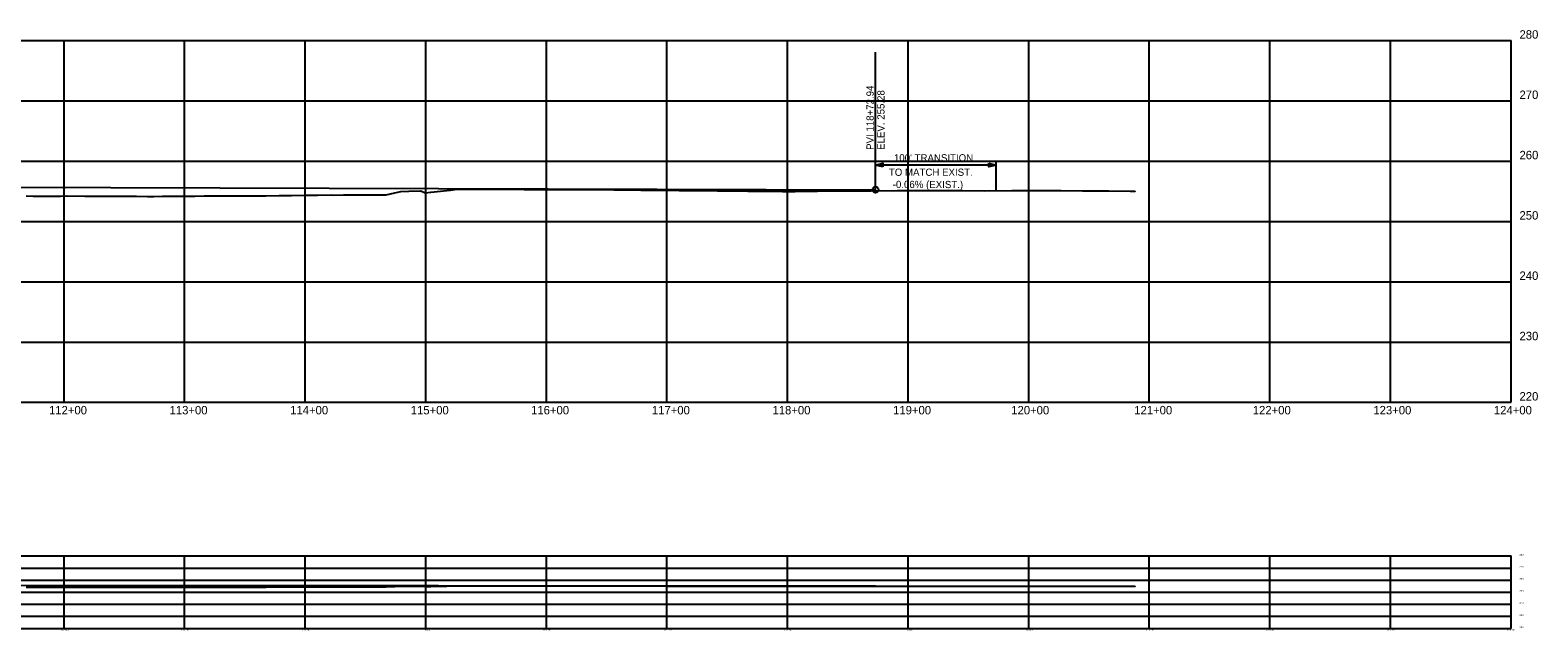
# Model space of a CAD drawing. Extents: x 1932071 to 1934815, y 598385 to 598883.
# Drawn here: x 1933565 to 1934815, y 598385 to 598883 of the extents above; entities that cross this region are included whole.
import ezdxf

# ---------------------------------------------------------------- set-up
doc = ezdxf.new("R2010")
doc.units = 0
for name, color, linetype in [('R_Annotation', 7, 'Continuous'), ('R_Axis', 7, 'Continuous'), ('R_Axis Annot', 7, 'Continuous'), ('R_Exist Surface', 7, 'Continuous'), ('R_Grid', 7, 'Continuous'), ('R_Vert Alg', 7, 'Continuous'), ('R_Vert Alg Annot', 7, 'Continuous')]:
    doc.layers.add(name, color=color, linetype=linetype)

msp = doc.modelspace()

# ---------------------------------------------------------------- linework, layer by layer
at = {"layer": 'R_Annotation'}
for p, q in [((1934265.6, 598750.9), (1934265.6, 598774.3)), ((1934365.6, 598771.3), (1934265.6, 598771.3)), ((1934365.6, 598750.9), (1934365.6, 598774.3))]:
    msp.add_line(p, q, dxfattribs=at)
for points in [[(1934271.6, 598769.8), (1934265.6, 598771.3), (1934271.6, 598772.8)], [(1934359.6, 598772.8), (1934365.6, 598771.3), (1934359.6, 598769.8)]]:
    msp.add_lwpolyline(points, close=True, dxfattribs=at)
at = {"layer": 'R_Axis'}
for p, q in [((1934392.7, 598874.6), (1934392.7, 598874.3)), ((1934792.7, 598574.6), (1934792.7, 598874.6)), ((1933692.7, 598824.6), (1933692.7, 598824.3)), ((1933692.7, 598824.6), (1933692.7, 598824.3)), ((1934192.7, 598824.6), (1934192.7, 598824.2)), ((1932092.7, 598574.6), (1934792.7, 598574.6)), ((1934392.7, 598447.2), (1934392.7, 598447.1)), ((1934392.7, 598447.2), (1934392.7, 598447.1)), ((1934792.7, 598387.2), (1934792.7, 598447.2)), ((1933692.7, 598437.2), (1933692.7, 598437.1)), ((1933692.7, 598437.2), (1933692.7, 598437.1)), ((1933692.7, 598437.2), (1933692.7, 598437.1)), ((1933692.7, 598437.2), (1933692.7, 598437.1)), ((1933692.7, 598437.2), (1933692.7, 598437.1)), ((1933692.7, 598437.2), (1933692.7, 598437.1)), ((1934192.7, 598437.2), (1934192.7, 598437.1)), ((1934192.7, 598437.2), (1934192.7, 598437.1)), ((1934192.7, 598437.2), (1934192.7, 598437.1)), ((1932092.7, 598387.2), (1934792.7, 598387.2))]:
    msp.add_line(p, q, dxfattribs=at)
at = {"layer": 'R_Exist Surface'}
for points in [[(1933561.3, 598745.7), (1933567.2, 598745.6), (1933584.5, 598745.5), (1933584.6, 598745.5), (1933584.8, 598745.5), (1933588.6, 598745.6), (1933589.6, 598745.6), (1933595, 598745.7), (1933595.3, 598745.7), (1933610, 598745.6), (1933612.3, 598745.6), (1933613.5, 598745.6), (1933629.9, 598745.5), (1933631.5, 598745.5), (1933632.5, 598745.5), (1933648, 598745.4), (1933652.9, 598745.4), (1933662, 598745.3), (1933667.1, 598745.3), (1933674.3, 598745.4), (1933682.7, 598745.5), (1933690.1, 598745.4), (1933695.7, 598745.5), (1933701.2, 598745.6), (1933709, 598745.7), (1933717.2, 598745.8), (1933722.5, 598745.8), (1933729, 598745.8), (1933729.5, 598745.8), (1933738.6, 598745.8), (1933750, 598745.8), (1933751.7, 598745.8), (1933760, 598745.9), (1933771.1, 598746.1), (1933773.3, 598746.1), (1933781.4, 598746.2), (1933792.2, 598746.4), (1933794.9, 598746.4), (1933802.9, 598746.4), (1933814.2, 598746.5), (1933816.1, 598746.4), (1933824.3, 598746.5), (1933836.4, 598746.6), (1933837.4, 598746.5), (1933845.7, 598746.6), (1933857.8, 598746.6), (1933859.9, 598746.6), (1933867.1, 598748.3), (1933872, 598749.4), (1933878.5, 598749.6), (1933888.4, 598750), (1933888.6, 598750), (1933892.1, 598748.2), (1933896.9, 598748.8), (1933910, 598750.2), (1933913.1, 598750.6), (1933915.1, 598750.8), (1933918.7, 598751.2), (1933931.4, 598751.3), (1933931.5, 598751.3), (1933936.9, 598751.3), (1933948.6, 598751.3), (1933952.9, 598751.3), (1933960.4, 598751.2), (1933966, 598751.2), (1933974.3, 598751.1), (1933982.6, 598751.1), (1933983.6, 598751.1), (1933983.8, 598751.1), (1933995.7, 598751.1), (1934002.5, 598751.1), (1934005, 598751.1), (1934017.1, 598751.1), (1934021.3, 598751.1), (1934026.3, 598751.1), (1934038.6, 598751), (1934041.3, 598751), (1934048.7, 598750.8), (1934057.2, 598750.7), (1934060, 598750.7), (1934071, 598750.6), (1934081.4, 598750.5), (1934081.7, 598750.5), (1934092.8, 598750.4), (1934102.8, 598750.3), (1934105.6, 598750.3), (1934114.6, 598750.2), (1934121.8, 598750.1), (1934124.3, 598750.1), (1934134.7, 598750), (1934140.7, 598749.9), (1934145.7, 598749.9), (1934154.9, 598749.9), (1934159.7, 598749.8), (1934167.1, 598749.7), (1934175.6, 598749.7), (1934179.4, 598749.6), (1934188.5, 598749.5), (1934196.3, 598749.5), (1934199.1, 598749.4), (1934217.6, 598749.7), (1934237.6, 598749.9), (1934238.8, 598749.9), (1934260.6, 598750), (1934261.2, 598750), (1934261.9, 598750), (1934283.6, 598750.1), (1934283.8, 598750.1), (1934301.7, 598750.1), (1934301.8, 598750.1), (1934319.8, 598750.1), (1934319.8, 598750.1), (1934329.2, 598750.1), (1934337.8, 598750.1), (1934337.9, 598750.1), (1934355.9, 598750), (1934355.9, 598750), (1934379, 598750.1), (1934379, 598750.1), (1934379, 598750.1), (1934386.6, 598750.1), (1934402, 598750.2), (1934402.1, 598750.2), (1934419.6, 598750.1), (1934419.7, 598750.1), (1934437.2, 598750), (1934437.2, 598750), (1934459, 598749.9), (1934476.7, 598749.7), (1934480.9, 598749.7), (1934480.9, 598749.7)], [(1933561.3, 598421.4), (1933567.2, 598421.4), (1933584.5, 598421.4), (1933584.6, 598421.4), (1933584.8, 598421.4), (1933588.6, 598421.4), (1933589.6, 598421.4), (1933595, 598421.4), (1933595.3, 598421.4), (1933610, 598421.4), (1933612.3, 598421.4), (1933613.5, 598421.4), (1933629.9, 598421.4), (1933631.5, 598421.4), (1933632.5, 598421.4), (1933648, 598421.3), (1933652.9, 598421.3), (1933662, 598421.3), (1933667.1, 598421.3), (1933674.3, 598421.3), (1933682.7, 598421.4), (1933690.1, 598421.3), (1933695.7, 598421.4), (1933701.2, 598421.4), (1933709, 598421.4), (1933717.2, 598421.4), (1933722.5, 598421.4), (1933729, 598421.4), (1933729.5, 598421.4), (1933738.6, 598421.4), (1933750, 598421.4), (1933751.7, 598421.4), (1933760, 598421.4), (1933771.1, 598421.5), (1933773.3, 598421.5), (1933781.4, 598421.5), (1933792.2, 598421.5), (1933794.9, 598421.5), (1933802.9, 598421.5), (1933814.2, 598421.6), (1933816.1, 598421.5), (1933824.3, 598421.6), (1933836.4, 598421.6), (1933837.4, 598421.6), (1933845.7, 598421.6), (1933857.8, 598421.6), (1933859.9, 598421.6), (1933867.1, 598421.9), (1933872, 598422.1), (1933878.5, 598422.2), (1933888.4, 598422.3), (1933888.6, 598422.3), (1933892.1, 598421.9), (1933896.9, 598422), (1933910, 598422.3), (1933913.1, 598422.4), (1933915.1, 598422.4), (1933918.7, 598422.5), (1933931.4, 598422.5), (1933931.5, 598422.5), (1933936.9, 598422.5), (1933948.6, 598422.5), (1933952.9, 598422.5), (1933960.4, 598422.5), (1933966, 598422.5), (1933974.3, 598422.5), (1933982.6, 598422.5), (1933983.6, 598422.5), (1933983.8, 598422.5), (1933995.7, 598422.5), (1934002.5, 598422.5), (1934005, 598422.5), (1934017.1, 598422.5), (1934021.3, 598422.5), (1934026.3, 598422.5), (1934038.6, 598422.5), (1934041.3, 598422.4), (1934048.7, 598422.4), (1934057.2, 598422.4), (1934060, 598422.4), (1934071, 598422.4), (1934081.4, 598422.4), (1934081.7, 598422.4), (1934092.8, 598422.3), (1934102.8, 598422.3), (1934105.6, 598422.3), (1934114.6, 598422.3), (1934121.8, 598422.3), (1934124.3, 598422.3), (1934134.7, 598422.3), (1934140.7, 598422.2), (1934145.7, 598422.2), (1934154.9, 598422.2), (1934159.7, 598422.2), (1934167.1, 598422.2), (1934175.6, 598422.2), (1934179.4, 598422.2), (1934188.5, 598422.2), (1934196.3, 598422.2), (1934199.1, 598422.1), (1934217.6, 598422.2), (1934237.6, 598422.2), (1934238.8, 598422.2), (1934260.6, 598422.3), (1934261.2, 598422.3), (1934261.9, 598422.3), (1934283.6, 598422.3), (1934283.8, 598422.3), (1934301.7, 598422.3), (1934301.8, 598422.3), (1934319.8, 598422.3), (1934319.8, 598422.3), (1934329.2, 598422.3), (1934337.8, 598422.3), (1934337.9, 598422.3), (1934355.9, 598422.3), (1934355.9, 598422.3), (1934379, 598422.3), (1934379, 598422.3), (1934379, 598422.3), (1934386.6, 598422.3), (1934402, 598422.3), (1934402.1, 598422.3), (1934419.6, 598422.3), (1934419.7, 598422.3), (1934437.2, 598422.3), (1934437.2, 598422.3), (1934459, 598422.2), (1934476.7, 598422.2), (1934480.9, 598422.2), (1934480.9, 598422.2)]]:
    msp.add_lwpolyline(points, dxfattribs=at)
at = {"layer": 'R_Grid'}
for p, q in [((1932092.7, 598874.6), (1934792.7, 598874.6)), ((1932092.7, 598874.6), (1934792.7, 598874.6)), ((1933592.7, 598574.6), (1933592.7, 598874.6)), ((1933692.7, 598574.6), (1933692.7, 598874.6)), ((1933792.7, 598574.6), (1933792.7, 598874.6)), ((1933892.7, 598574.6), (1933892.7, 598874.6)), ((1933992.7, 598574.6), (1933992.7, 598874.6)), ((1934092.7, 598574.6), (1934092.7, 598874.6)), ((1934192.7, 598574.6), (1934192.7, 598874.6)), ((1934292.7, 598574.6), (1934292.7, 598874.6)), ((1934392.7, 598574.6), (1934392.7, 598874.6)), ((1934492.7, 598574.6), (1934492.7, 598874.6)), ((1934592.7, 598574.6), (1934592.7, 598874.6)), ((1934692.7, 598574.6), (1934692.7, 598874.6)), ((1932092.7, 598824.6), (1934792.7, 598824.6)), ((1932092.7, 598774.6), (1934792.7, 598774.6)), ((1932092.7, 598724.6), (1934792.7, 598724.6)), ((1932092.7, 598674.6), (1934792.7, 598674.6)), ((1932092.7, 598624.6), (1934792.7, 598624.6)), ((1932092.7, 598447.2), (1934792.7, 598447.2)), ((1932092.7, 598447.2), (1934792.7, 598447.2)), ((1933592.7, 598387.2), (1933592.7, 598447.2)), ((1933692.7, 598387.2), (1933692.7, 598447.2)), ((1933792.7, 598387.2), (1933792.7, 598447.2)), ((1933892.7, 598387.2), (1933892.7, 598447.2)), ((1933992.7, 598387.2), (1933992.7, 598447.2)), ((1934092.7, 598387.2), (1934092.7, 598447.2)), ((1934192.7, 598387.2), (1934192.7, 598447.2)), ((1934292.7, 598387.2), (1934292.7, 598447.2)), ((1934392.7, 598387.2), (1934392.7, 598447.2)), ((1934492.7, 598387.2), (1934492.7, 598447.2)), ((1934592.7, 598387.2), (1934592.7, 598447.2)), ((1934692.7, 598387.2), (1934692.7, 598447.2)), ((1932092.7, 598437.2), (1934792.7, 598437.2)), ((1932092.7, 598427.2), (1934792.7, 598427.2)), ((1932092.7, 598417.2), (1934792.7, 598417.2)), ((1932092.7, 598407.2), (1934792.7, 598407.2)), ((1932092.7, 598397.2), (1934792.7, 598397.2))]:
    msp.add_line(p, q, dxfattribs=at)
at = {"layer": 'R_Vert Alg'}
for p, q in [((1933540.7, 598753.1), (1934265.6, 598750.9)), ((1933540.7, 598422.9), (1934265.6, 598422.4))]:
    msp.add_line(p, q, dxfattribs=at)
at = {"layer": 'R_Vert Alg Annot'}
for p, q in [((1934265.6, 598780.9), (1934265.6, 598864.9)), ((1934265.6, 598750.9), (1934265.6, 598780.9))]:
    msp.add_line(p, q, dxfattribs=at)
msp.add_circle((1934265.6, 598750.9), 2.5, dxfattribs=at)

# ---------------------------------------------------------------- texts
at = {"layer": 'R_Annotation'}
for s, p in [('TO MATCH EXIST.', (1934276.7, 598762.4)), ("100' TRANSITION", (1934280.9, 598774.3))]:
    msp.add_text(s, height=6, rotation=0.0048, dxfattribs=at).set_placement(p)
at = {"layer": 'R_Axis Annot'}
for s, height, p in [('280', 7, (1934799.7, 598876.1)), ('280', 7, (1934799.7, 598876.1)), ('270', 7, (1934799.7, 598826.1)), ('260', 7, (1934799.7, 598776.1)), ('250', 7, (1934799.7, 598726.1)), ('240', 7, (1934799.7, 598676.1)), ('230', 7, (1934799.7, 598626.1)), ('220', 7, (1934799.7, 598576.1)), ('112+00', 7, (1933580.2, 598564.6)), ('113+00', 7, (1933680.2, 598564.6)), ('114+00', 7, (1933780.2, 598564.6)), ('115+00', 7, (1933880.2, 598564.6)), ('116+00', 7, (1933980, 598564.6)), ('117+00', 7, (1934080.2, 598564.6)), ('118+00', 7, (1934180.2, 598564.6)), ('119+00', 7, (1934280.2, 598564.6)), ('120+00', 7, (1934378.2, 598564.6)), ('121+00', 7, (1934480.2, 598564.6)), ('122+00', 7, (1934578.5, 598564.6)), ('123+00', 7, (1934678.5, 598564.6)), ('124+00', 7, (1934778.5, 598564.6)), ('280', 1.4, (1934799.7, 598447.5)), ('280', 1.4, (1934799.7, 598447.5)), ('270', 1.4, (1934799.7, 598437.5)), ('260', 1.4, (1934799.7, 598427.5)), ('250', 1.4, (1934799.7, 598417.5)), ('240', 1.4, (1934799.7, 598407.5)), ('230', 1.4, (1934799.7, 598397.5)), ('112+00', 1.4, (1933589.8, 598385.2)), ('113+00', 1.4, (1933689.8, 598385.2)), ('114+00', 1.4, (1933789.8, 598385.2)), ('115+00', 1.4, (1933889.8, 598385.2)), ('116+00', 1.4, (1933989.7, 598385.2)), ('117+00', 1.4, (1934089.8, 598385.2)), ('118+00', 1.4, (1934189.8, 598385.2)), ('119+00', 1.4, (1934289.8, 598385.2)), ('120+00', 1.4, (1934389.3, 598385.2)), ('121+00', 1.4, (1934489.8, 598385.2)), ('122+00', 1.4, (1934589.4, 598385.2)), ('123+00', 1.4, (1934689.4, 598385.2)), ('124+00', 1.4, (1934789.4, 598385.2)), ('220', 1.4, (1934799.7, 598387.5))]:
    msp.add_text(s, height=height, dxfattribs=at).set_placement(p)
at = {"layer": 'R_Vert Alg Annot'}
for s, rotation, p in [('PVI 118+72.94', 90, (1934264.1, 598783.9)), ('ELEV. 255.28', 90, (1934273.1, 598783.9)), ('-0.06% (EXIST.)', 359.8731, (1934279.9, 598752.3))]:
    msp.add_text(s, height=6, rotation=rotation, dxfattribs=at).set_placement(p)

doc.saveas('drawing.dxf')
